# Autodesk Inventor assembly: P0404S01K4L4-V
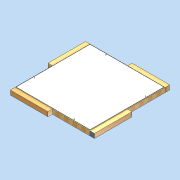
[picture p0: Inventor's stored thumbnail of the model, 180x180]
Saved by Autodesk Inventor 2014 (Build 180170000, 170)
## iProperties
Created: 2011-04
Part Number: P0404S01K4L4-V
Document SubType Name: Assembly
Designer: david.appleford
Description: 1w x 1w 01 Panel 4 Locks 4 Lugs
Mass: 26000 g
Surface Area: 36857.6 cm^2
Volume: 116251 cm^3
Density: 0.223654 g/cm^3
Cost Center: £107.00
Justset: False
Title: 1w x 1w 01 Panel 4 Locks 4 Lugs
Author: david.appleford
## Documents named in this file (3)
- C:\Documents and Settings\john.everitt\Local Settings\My Documents\Vault\Production MkII\Virtual Elements\Virtual Walls\Virtual Timber + MgO\P0404S01K4L4-V.iam
- C:\Documents and Settings\john.everitt\Local Settings\My Documents\Vault\Production MkII\VIRTUAL ELEMENTS\Virtual Lugs\Superceded Lugs\LA02C3V.ipt
- C:\Documents and Settings\john.everitt\Local Settings\My Documents\Vault\Production MkII\Virtual Elements\Virtual Walls\Virtual Timber + MgO\P0404S01K4-V.ipt
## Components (5 placed, 2 different names)
1. P0404S01K4-V:1 — Mate:1, Flush:1, Flush:2, Mate:2, Flush:3, Flush:4, Mate:4, Flush:7, Flush:8, Mate:5, Flush:10
2. LA02C3V:1 — Mate:1, Flush:1, Flush:2, Mate:13
3. LA02C3V:2 — Mate:2, Flush:3, Flush:4
4. LA02C3V:3 — Mate:4, Flush:7, Flush:8
5. LA02C3V:4 — Mate:5, Flush:10, Mate:13
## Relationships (12: Flush 7, Mate 5)
- Mate:1: P0404S01K4-V:1 ↔ LA02C3V:1
- Flush:1: P0404S01K4-V:1 ↔ LA02C3V:1
- Flush:2: P0404S01K4-V:1 ↔ LA02C3V:1
- Mate:2: P0404S01K4-V:1 ↔ LA02C3V:2
- Flush:3: P0404S01K4-V:1 ↔ LA02C3V:2
- Flush:4: P0404S01K4-V:1 ↔ LA02C3V:2
- Mate:4: P0404S01K4-V:1 ↔ LA02C3V:3
- Flush:7: P0404S01K4-V:1 ↔ LA02C3V:3
- Flush:8: P0404S01K4-V:1 ↔ LA02C3V:3
- Mate:5: P0404S01K4-V:1 ↔ LA02C3V:4
- Flush:10: P0404S01K4-V:1 ↔ LA02C3V:4
- Mate:13: LA02C3V:1 ↔ LA02C3V:4
## Named parameters: t = 1 mm, Cl = 2 mm
